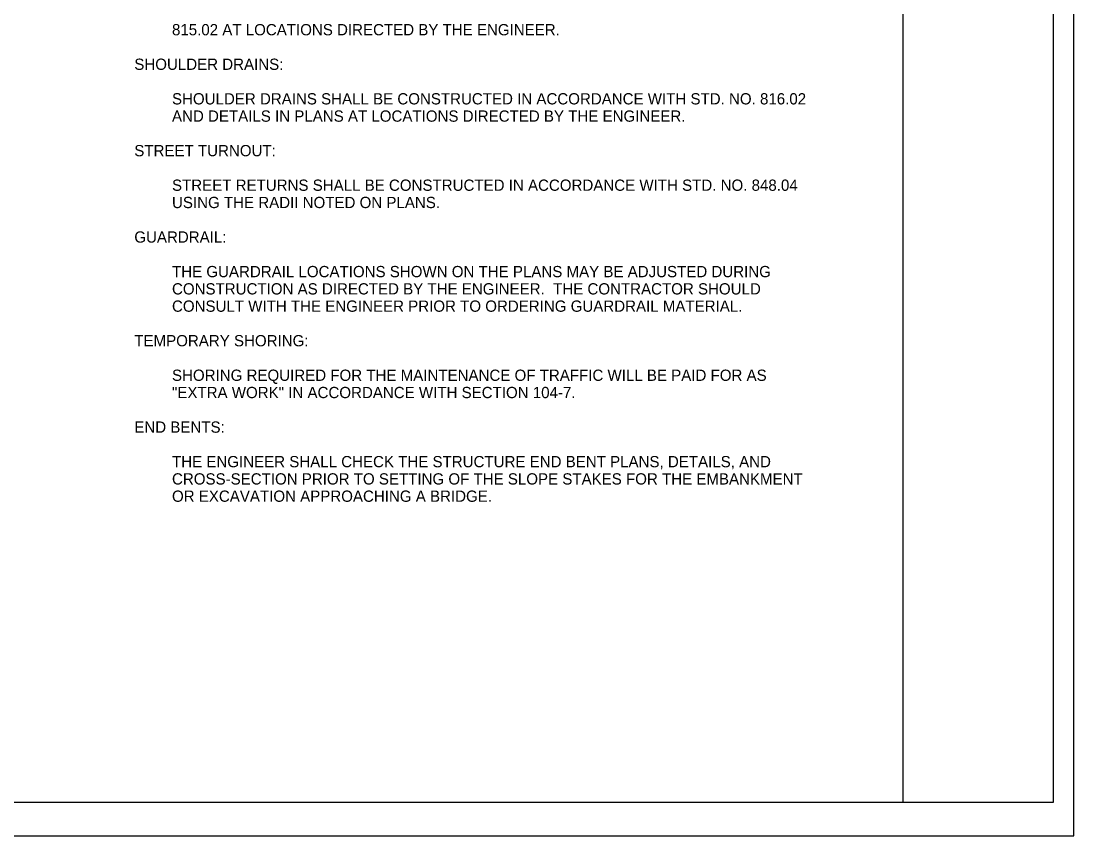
# Model space of a CAD drawing. Extents: x 1552903 to 1553045, y 811348 to 811440.
# Drawn here: x 1552986.4 to 1553044.8, y 811348.3 to 811393.5 of the extents above; entities that cross this region are included whole.
import ezdxf

# ---------------------------------------------------------------- set-up
doc = ezdxf.new("R2010")
doc.units = 0
for name, color, linetype in [('Prop Terminator CELL', 7, 'Continuous'), ('Sheet Plan CELL', 7, 'Continuous'), ('Typical Terminator CELL', 7, 'Continuous'), ('z - Construction', 7, 'Continuous')]:
    doc.layers.add(name, color=color, linetype=linetype)

msp = doc.modelspace()

# ---------------------------------------------------------------- linework, layer by layer
at = {"layer": 'Prop Terminator CELL'}
for p, q in [((1553043.689, 811350.208), (1553043.691, 811438.123)), ((1552906.189, 811350.208), (1553043.689, 811350.208))]:
    msp.add_line(p, q, dxfattribs=at)
at = {"layer": 'Typical Terminator CELL'}
for p, q in [((1553044.816, 811348.333), (1553044.816, 811439.998)), ((1552903.151, 811348.333), (1553044.816, 811348.333))]:
    msp.add_line(p, q, dxfattribs=at)
at = {"layer": 'z - Construction'}
msp.add_line((1553035.356, 811350.208), (1553035.358, 811438.123), dxfattribs=at)

# ---------------------------------------------------------------- texts
at = {"layer": 'Sheet Plan CELL'}
for s, p in [('         815.02 AT LOCATIONS DIRECTED BY THE ENGINEER.  ', (1552992.723, 811392.742)), ('SHOULDER DRAINS:  ', (1552992.723, 811390.825)), ('         SHOULDER DRAINS SHALL BE CONSTRUCTED IN ACCORDANCE WITH STD. NO. 816.02 ', (1552992.723, 811388.908)), ('         AND DETAILS IN PLANS AT LOCATIONS DIRECTED BY THE ENGINEER.  ', (1552992.723, 811387.95)), ('STREET TURNOUT:  ', (1552992.723, 811386.033)), ('         STREET RETURNS SHALL BE CONSTRUCTED IN ACCORDANCE WITH STD. NO. 848.04  ', (1552992.723, 811384.117)), ('         USING THE RADII NOTED ON PLANS.  ', (1552992.723, 811383.158)), ('GUARDRAIL:  ', (1552992.723, 811381.242)), ('         THE GUARDRAIL LOCATIONS SHOWN ON THE PLANS MAY BE ADJUSTED DURING ', (1552992.723, 811379.325)), ('         CONSTRUCTION AS DIRECTED BY THE ENGINEER.  THE CONTRACTOR SHOULD ', (1552992.723, 811378.367)), ('         CONSULT WITH THE ENGINEER PRIOR TO ORDERING GUARDRAIL MATERIAL.', (1552992.723, 811377.408)), ('TEMPORARY SHORING:  ', (1552992.723, 811375.492)), ('         SHORING REQUIRED FOR THE MAINTENANCE OF TRAFFIC WILL BE PAID FOR AS  ', (1552992.723, 811373.575)), ('         "EXTRA WORK" IN ACCORDANCE WITH SECTION 104-7.  ', (1552992.723, 811372.617)), ('END BENTS:  ', (1552992.723, 811370.7)), ('         THE ENGINEER SHALL CHECK THE STRUCTURE END BENT PLANS, DETAILS, AND ', (1552992.723, 811368.783)), ('         CROSS-SECTION PRIOR TO SETTING OF THE SLOPE STAKES FOR THE EMBANKMENT  ', (1552992.723, 811367.825)), ('         OR EXCAVATION APPROACHING A BRIDGE.  ', (1552992.723, 811366.867))]:
    msp.add_text(s, height=0.625, dxfattribs=at).set_placement(p)

doc.saveas('drawing.dxf')
